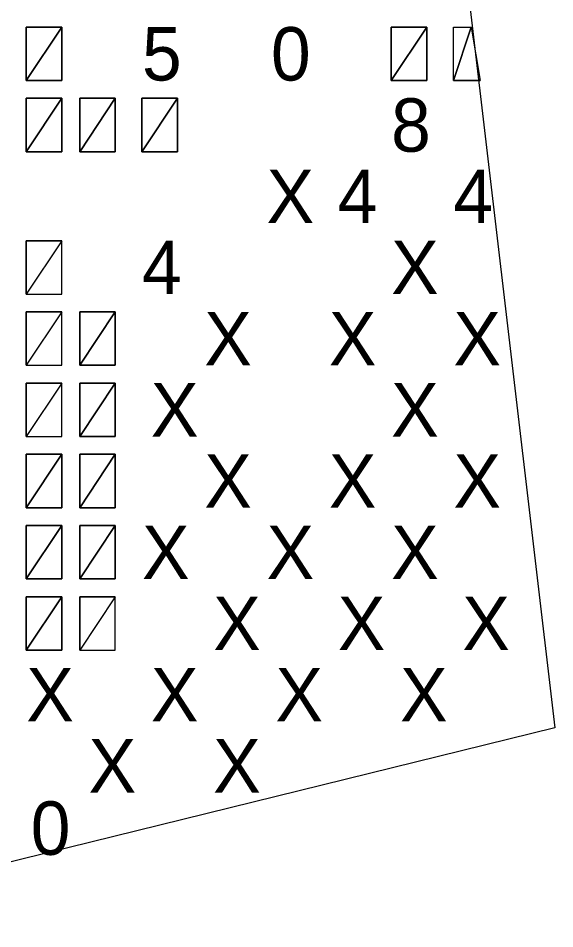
# Model space of a CAD drawing. Extents: x 0 to 34, y 0 to 22.
# Drawn here: x 4.554 to 4.7256, y 2.1022 to 2.3933 of the extents above; entities that cross this region are included whole.
import ezdxf

# ---------------------------------------------------------------- set-up
doc = ezdxf.new("R2010")
doc.units = 0
doc.layers.add('SH_Text', color=7, linetype='Continuous')

msp = doc.modelspace()

# ---------------------------------------------------------------- linework, layer by layer
at = {"layer": 'SH_Text'}
for p, q in [((4.66715, 2.66362), (4.72559, 2.16645)), ((4.5566, 2.39044), (4.5566, 2.37337)), ((4.56798, 2.39044), (4.5566, 2.39044)), ((4.56798, 2.37337), (4.56798, 2.39044)), ((4.68463, 2.39044), (4.67325, 2.39044)), ((4.67325, 2.39044), (4.67325, 2.37337)), ((4.68463, 2.37337), (4.68463, 2.39044)), ((4.69317, 2.39044), (4.69886, 2.39044)), ((4.69317, 2.37337), (4.69317, 2.39044)), ((4.5566, 2.37337), (4.56798, 2.37337)), ((4.67325, 2.37337), (4.68463, 2.37337)), ((4.69317, 2.37337), (4.7017, 2.37337)), ((4.56798, 2.36768), (4.5566, 2.36768)), ((4.5566, 2.36768), (4.5566, 2.35061)), ((4.56798, 2.35061), (4.56798, 2.36768)), ((4.57367, 2.36768), (4.57367, 2.35061)), ((4.58505, 2.36768), (4.57367, 2.36768)), ((4.58505, 2.35061), (4.58505, 2.36768)), ((4.60497, 2.36768), (4.59359, 2.36768)), ((4.59359, 2.36768), (4.59359, 2.35061)), ((4.60497, 2.35061), (4.60497, 2.36768)), ((4.5566, 2.35061), (4.56798, 2.35061)), ((4.57367, 2.35061), (4.58505, 2.35061)), ((4.59359, 2.35061), (4.60497, 2.35061)), ((4.5566, 2.32215), (4.5566, 2.30508)), ((4.56798, 2.32215), (4.5566, 2.32215)), ((4.56798, 2.30508), (4.56798, 2.32215)), ((4.5566, 2.30508), (4.56798, 2.30508)), ((4.56798, 2.29939), (4.5566, 2.29939)), ((4.5566, 2.29939), (4.5566, 2.28232)), ((4.56798, 2.28232), (4.56798, 2.29939)), ((4.57367, 2.29939), (4.57367, 2.28232)), ((4.58505, 2.29939), (4.57367, 2.29939)), ((4.58505, 2.28232), (4.58505, 2.29939)), ((4.5566, 2.28232), (4.56798, 2.28232)), ((4.57367, 2.28232), (4.58505, 2.28232)), ((4.56798, 2.27663), (4.5566, 2.27663)), ((4.5566, 2.27663), (4.5566, 2.25956)), ((4.56798, 2.25956), (4.56798, 2.27663)), ((4.58505, 2.27663), (4.57367, 2.27663)), ((4.57367, 2.27663), (4.57367, 2.25956)), ((4.58505, 2.25956), (4.58505, 2.27663)), ((4.5566, 2.25956), (4.56798, 2.25956)), ((4.57367, 2.25956), (4.58505, 2.25956)), ((4.5566, 2.25387), (4.5566, 2.2368)), ((4.56798, 2.25387), (4.5566, 2.25387)), ((4.56798, 2.2368), (4.56798, 2.25387)), ((4.58505, 2.25387), (4.57367, 2.25387)), ((4.57367, 2.25387), (4.57367, 2.2368)), ((4.58505, 2.2368), (4.58505, 2.25387)), ((4.5566, 2.2368), (4.56798, 2.2368)), ((4.57367, 2.2368), (4.58505, 2.2368)), ((4.56798, 2.23111), (4.5566, 2.23111)), ((4.5566, 2.23111), (4.5566, 2.21404)), ((4.56798, 2.21404), (4.56798, 2.23111)), ((4.57367, 2.23111), (4.57367, 2.21404)), ((4.58505, 2.23111), (4.57367, 2.23111)), ((4.58505, 2.21404), (4.58505, 2.23111)), ((4.5566, 2.21404), (4.56798, 2.21404)), ((4.57367, 2.21404), (4.58505, 2.21404)), ((4.56798, 2.20835), (4.5566, 2.20835)), ((4.5566, 2.20835), (4.5566, 2.19127)), ((4.56798, 2.19127), (4.56798, 2.20835)), ((4.57367, 2.20835), (4.57367, 2.19127)), ((4.58505, 2.20835), (4.57367, 2.20835)), ((4.58505, 2.19127), (4.58505, 2.20835)), ((4.5566, 2.19127), (4.56798, 2.19127)), ((4.57367, 2.19127), (4.58505, 2.19127)), ((4.72559, 2.16645), (4.46478, 2.10219))]:
    msp.add_line(p, q, dxfattribs=at)
for points in [[(4.5566, 2.37337), (4.5566, 2.39044), (4.56798, 2.39044)], [(4.56798, 2.39044), (4.56798, 2.37337), (4.5566, 2.37337)], [(4.56798, 2.39044), (4.56798, 2.39044), (4.56798, 2.39044)], [(4.67325, 2.37337), (4.67325, 2.39044), (4.68463, 2.39044)], [(4.68463, 2.39044), (4.68463, 2.37337), (4.67325, 2.37337)], [(4.69317, 2.37337), (4.69317, 2.39044), (4.69886, 2.39044)], [(4.69886, 2.39044), (4.7017, 2.37337), (4.69317, 2.37337)], [(4.56798, 2.36768), (4.56798, 2.35061), (4.5566, 2.35061)], [(4.5566, 2.35061), (4.5566, 2.36768), (4.56798, 2.36768)], [(4.56798, 2.36768), (4.56798, 2.36768), (4.56798, 2.36768)], [(4.58505, 2.36768), (4.58505, 2.35061), (4.57367, 2.35061)], [(4.57367, 2.35061), (4.57367, 2.36768), (4.58505, 2.36768)], [(4.59359, 2.35061), (4.59359, 2.36768), (4.60497, 2.36768)], [(4.60497, 2.36768), (4.60497, 2.35061), (4.59359, 2.35061)], [(4.5566, 2.30508), (4.5566, 2.32215), (4.56798, 2.32215)], [(4.5566, 2.30508), (4.56798, 2.30508), (4.56798, 2.32215)], [(4.5566, 2.28232), (4.56798, 2.28232), (4.56798, 2.29939)], [(4.5566, 2.28232), (4.5566, 2.29939), (4.56798, 2.29939)], [(4.58505, 2.29939), (4.58505, 2.28232), (4.57367, 2.28232)], [(4.57367, 2.28232), (4.57367, 2.29939), (4.58505, 2.29939)], [(4.5566, 2.25956), (4.56798, 2.25956), (4.56798, 2.27663)], [(4.5566, 2.25956), (4.5566, 2.27663), (4.56798, 2.27663)], [(4.57367, 2.25956), (4.57367, 2.27663), (4.58505, 2.27663)], [(4.58505, 2.27663), (4.58505, 2.25956), (4.57367, 2.25956)], [(4.5566, 2.2368), (4.5566, 2.25387), (4.56798, 2.25387)], [(4.56798, 2.25387), (4.56798, 2.2368), (4.5566, 2.2368)], [(4.56798, 2.25387), (4.56798, 2.25387), (4.56798, 2.25387)], [(4.57367, 2.2368), (4.57367, 2.25387), (4.58505, 2.25387)], [(4.58505, 2.25387), (4.58505, 2.2368), (4.57367, 2.2368)], [(4.56798, 2.23111), (4.56798, 2.21404), (4.5566, 2.21404)], [(4.5566, 2.21404), (4.5566, 2.23111), (4.56798, 2.23111)], [(4.56798, 2.23111), (4.56798, 2.23111), (4.56798, 2.23111)], [(4.58505, 2.23111), (4.58505, 2.21404), (4.57367, 2.21404)], [(4.57367, 2.21404), (4.57367, 2.23111), (4.58505, 2.23111)], [(4.5566, 2.19127), (4.5566, 2.20835), (4.56798, 2.20835)], [(4.56798, 2.20835), (4.56798, 2.19127), (4.5566, 2.19127)], [(4.57367, 2.19127), (4.57367, 2.20835), (4.58505, 2.20835)], [(4.57367, 2.19127), (4.58505, 2.19127), (4.58505, 2.20835)]]:
    msp.add_lwpolyline(points, close=True, dxfattribs=at)

# ---------------------------------------------------------------- texts
for s, p in [('5', (4.59359, 2.37337)), ('0', (4.63484, 2.37337)), ('8', (4.67325, 2.35061)), ('X', (4.63342, 2.32784)), ('4', (4.65618, 2.32784)), ('4', (4.69317, 2.32784)), ('4', (4.59359, 2.30508)), ('X', (4.67325, 2.30508)), ('X', (4.6135, 2.28232)), ('X', (4.65333, 2.28232)), ('X', (4.69317, 2.28232)), ('X', (4.59643, 2.25956)), ('X', (4.67325, 2.25956)), ('X', (4.6135, 2.2368)), ('X', (4.65333, 2.2368)), ('X', (4.69317, 2.2368)), ('X', (4.59359, 2.21404)), ('X', (4.63342, 2.21404)), ('X', (4.67325, 2.21404)), ('X', (4.61635, 2.19127)), ('X', (4.65618, 2.19127)), ('X', (4.69601, 2.19127)), ('X', (4.5566, 2.16851)), ('X', (4.59643, 2.16851)), ('X', (4.63626, 2.16851)), ('X', (4.6761, 2.16851)), ('X', (4.57651, 2.14575)), ('X', (4.61635, 2.14575)), ('0', (4.55802, 2.12584))]:
    msp.add_text(s, height=0.01707, dxfattribs=at).set_placement(p)

doc.saveas('drawing.dxf')
